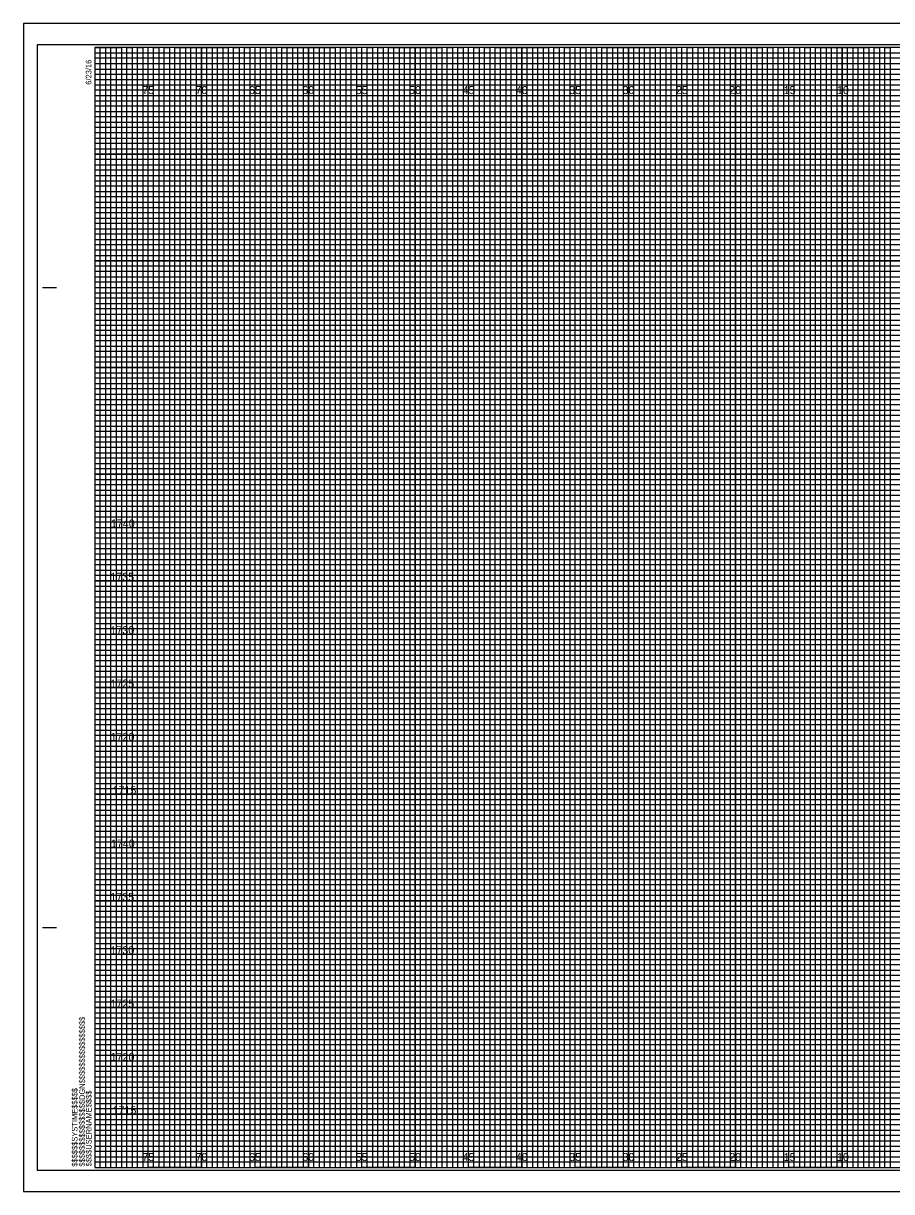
# Model space of a CAD drawing. Extents: x -7 to 162, y -2 to 327.
# Drawn here: x -6.7 to 74.6, y 217.7 to 327.2 of the extents above; entities that cross this region are included whole.
import ezdxf

# ---------------------------------------------------------------- set-up
doc = ezdxf.new("R2010")
doc.units = 0
for name, color, linetype in [('Prop XS Elevation Labels', 7, 'Continuous'), ('Prop XS Offset Labels', 7, 'Continuous'), ('Sheet Cross Section CELL', 7, 'Continuous'), ('Sheet Cross Section Grid Major CELL', 7, 'Continuous'), ('Sheet Cross Section Grid Middle CELL', 7, 'Continuous'), ('Sheet Cross Section Grid Minor 1 CELL', 7, 'Continuous'), ('Sheet Cross Section Grid Minor 2 CELL', 7, 'Continuous'), ('Sheet Cutting Line CELL', 7, 'Continuous'), ('Sheet DOT Grid CELL', 7, 'Continuous'), ('Sheet Plot Border Inside CELL', 7, 'Continuous'), ('Sheet Plot Border Outside CELL', 7, 'Continuous')]:
    doc.layers.add(name, color=color, linetype=linetype)

msp = doc.modelspace()

# ---------------------------------------------------------------- linework, layer by layer
at = {"layer": 'Sheet Cross Section CELL'}
for p, q in [((-4.9, 302.5), (-3.65, 302.5)), ((-4.85, 302.5), (-3.6, 302.5)), ((-4.9, 242.5), (-3.65, 242.5)), ((-4.85, 242.5), (-3.6, 242.5)), ((0, 220), (0, 220)), ((0, 220), (0, 220)), ((0, 220), (0, 220)), ((0, 220), (0, 220)), ((0, 220), (0, 220)), ((0, 220), (0, 220)), ((0, 220), (0, 220))]:
    msp.add_line(p, q, dxfattribs=at)
msp.add_lwpolyline([(160, 325), (0, 325), (0, 220), (160, 220)], close=True, dxfattribs=at)
at = {"layer": 'Sheet Cross Section Grid Major CELL'}
for p, q in [((5, 325), (0, 325)), ((5, 220), (5, 325)), ((15, 325), (10, 325)), ((10, 325), (10, 220)), ((15, 220), (15, 325)), ((25, 325), (20, 325)), ((20, 325), (20, 220)), ((25, 220), (25, 325)), ((35, 325), (30, 325)), ((30, 325), (30, 220)), ((35, 220), (35, 325)), ((45, 325), (40, 325)), ((40, 325), (40, 220)), ((45, 220), (45, 325)), ((55, 325), (50, 325)), ((50, 325), (50, 220)), ((55, 220), (55, 325)), ((65, 325), (60, 325)), ((60, 325), (60, 220)), ((65, 220), (65, 325)), ((75, 325), (70, 325)), ((70, 325), (70, 220)), ((10, 220), (5, 220)), ((20, 220), (15, 220)), ((30, 220), (25, 220)), ((40, 220), (35, 220)), ((50, 220), (45, 220)), ((60, 220), (55, 220)), ((70, 220), (65, 220))]:
    msp.add_line(p, q, dxfattribs=at)
for points in [[(0, 320), (160, 320), (160, 315), (0, 315)], [(0, 310), (160, 310), (160, 305), (0, 305)], [(0, 300), (160, 300), (160, 295), (0, 295)], [(0, 290), (160, 290), (160, 285), (0, 285)], [(0, 280), (160, 280), (160, 275), (0, 275)], [(0, 270), (160, 270), (160, 265), (0, 265)], [(0, 260), (160, 260), (160, 255), (0, 255)], [(0, 250), (160, 250), (160, 245), (0, 245)], [(0, 240), (160, 240), (160, 235), (0, 235)], [(0, 230), (160, 230), (160, 225), (0, 225)]]:
    msp.add_lwpolyline(points, dxfattribs=at)
at = {"layer": 'Sheet Cross Section Grid Middle CELL'}
for points in [[(0, 325), (2.5, 325), (2.5, 220), (7.5, 220), (7.5, 325), (12.5, 325), (12.5, 220), (17.5, 220), (17.5, 325), (22.5, 325), (22.5, 220), (27.5, 220), (27.5, 325), (32.5, 325), (32.5, 220), (37.5, 220), (37.5, 325), (42.5, 325), (42.5, 220), (47.5, 220), (47.5, 325), (52.5, 325), (52.5, 220), (57.5, 220), (57.5, 325), (62.5, 325), (62.5, 220), (67.5, 220), (67.5, 325), (72.5, 325), (72.5, 220), (77.5, 220)], [(0, 322.5), (137.5, 322.5)], [(0, 312.5), (160, 312.5), (160, 317.5), (0, 317.5)], [(0, 302.5), (160, 302.5), (160, 307.5), (0, 307.5)], [(0, 292.5), (160, 292.5), (160, 297.5), (0, 297.5)], [(0, 282.5), (160, 282.5), (160, 287.5), (0, 287.5)], [(0, 272.5), (160, 272.5), (160, 277.5), (0, 277.5)], [(0, 262.5), (160, 262.5), (160, 267.5), (0, 267.5)], [(0, 252.5), (160, 252.5), (160, 257.5), (0, 257.5)], [(0, 242.5), (160, 242.5), (160, 247.5), (0, 247.5)], [(0, 232.5), (160, 232.5), (160, 237.5), (0, 237.5)], [(0, 222.5), (160, 222.5), (160, 227.5), (0, 227.5)]]:
    msp.add_lwpolyline(points, dxfattribs=at)
at = {"layer": 'Sheet Cross Section Grid Minor 1 CELL'}
for p, q in [((0, 324.5), (130, 324.5)), ((130, 323.99), (0, 323.99)), ((0, 323.99), (0, 323.5)), ((0, 323.5), (130, 323.5)), ((130, 322.94), (0, 322.94)), ((0, 322.94), (0, 322)), ((0, 322), (160, 322))]:
    msp.add_line(p, q, dxfattribs=at)
for points in [[(0, 321.5), (135, 321.5), (160, 321.5), (160, 321), (0, 321)], [(0, 320.5), (160, 320.5), (160, 319.5), (0, 319.5)], [(0, 319), (160, 319), (160, 318.5), (0, 318.49)], [(0, 318), (160, 318), (160, 317), (0, 317)], [(0, 316.5), (160, 316.5), (160, 316), (0, 316)], [(0, 315.5), (160, 315.5), (160, 314.5), (0, 314.5)], [(0, 314), (160, 314), (160, 313.5), (0, 313.5)], [(0, 313), (160, 313), (160, 312), (0, 312)], [(0, 311.5), (160, 311.5), (160, 311), (0, 311)], [(0, 310.5), (160, 310.5), (160, 309.5), (0, 309.5)], [(0, 309), (160, 309), (160, 308.5), (0, 308.5)], [(0, 308), (160, 308), (160, 306.98), (160, 306.5), (160, 306), (0, 306)], [(0, 307), (160, 307), (160, 306.5), (0, 306.5)], [(0, 305.5), (160, 305.5), (160, 304.5), (0, 304.51)], [(0, 304.51), (160, 304.5), (160, 304), (0, 304)], [(0, 303.5), (160, 303.5), (160, 303), (0, 303)], [(0, 302), (160, 302), (160, 301.5), (0, 301.5)], [(0, 301), (160, 301), (160, 300.5), (0, 300.5)], [(-0.04, 299.44), (160, 299.44), (160, 298.94), (-0.04, 298.94)], [(0, 298.5), (160, 298.5), (160, 298), (0, 298)], [(0, 297), (160, 297), (160, 296.5), (0, 296.5)], [(0, 296), (160, 296), (160, 295.5), (0, 295.5)], [(0, 294.5), (160, 294.5), (160, 294), (0, 294)], [(0, 293.5), (160, 293.5), (160, 293), (0, 293)], [(0, 292), (160, 292), (160, 291.5), (0, 291.5)], [(0, 291), (160, 291), (160, 290.5), (0, 290.5)], [(0, 289.5), (160, 289.5), (160, 288.99), (0, 289)], [(0, 288.5), (160, 288.5), (160, 288), (0, 288)], [(0, 287), (160, 287), (160, 286.5), (0, 286.5)], [(0, 286), (160, 286), (160, 285.5), (0, 285.5)], [(0, 284.5), (160, 284.5), (160, 284), (0, 284)], [(0, 283.5), (160, 283.5), (160, 283), (0, 283)], [(0, 282), (160, 282), (160, 281.5), (0, 281.5)], [(0, 281), (160, 281), (160, 280.5), (0, 280.5)], [(0, 279.5), (160, 279.5), (160, 279), (0, 279)], [(0, 278.5), (160.03, 278.45), (160, 278), (0, 278)], [(0, 277), (160, 277), (160, 276.5), (0, 276.5)], [(0, 276), (160, 276), (160, 275.5), (0, 275.5)], [(0, 274.5), (160, 274.5), (160, 274), (0, 274)], [(0, 273.5), (160, 273.5), (160, 273), (0, 273)], [(0, 272), (160, 272), (160, 271.5), (0, 271.5)], [(0, 271), (160, 271), (160, 270.5), (0, 270.5)], [(0, 269.5), (160, 269.5), (160, 269), (0, 269)], [(0, 268.5), (160, 268.5), (160, 268), (0, 268)], [(0, 267), (160, 267), (160, 266.5), (0, 266.5)], [(0, 266), (160, 266), (160, 265.5), (0, 265.5)], [(0, 264.5), (160, 264.5), (160, 264), (0, 264)], [(0, 263.5), (160, 263.5), (160, 263), (0, 263)], [(0, 262), (160, 262), (160, 261.5), (0, 261.5)], [(0, 261), (160, 261), (160, 260.5), (0, 260.5)], [(0, 259.5), (160, 259.5), (160, 258.99), (0, 259)], [(0, 258.5), (160, 258.5), (160, 258), (0, 258)], [(0, 257), (160, 257), (160, 256.5), (0, 256.5)], [(0, 256), (160, 256), (160, 255.5), (0, 255.5)], [(0, 254.5), (160, 254.5), (160, 254), (0, 254)], [(0, 253.5), (160, 253.5), (160, 253), (0, 253)], [(0, 252), (160, 252), (160, 251.5), (0, 251.5)], [(0, 251), (160, 251), (160, 250.5), (0, 250.5)], [(0, 249.5), (160, 249.5), (160, 249), (0, 249)], [(0, 248.5), (160.03, 248.46), (160, 248), (0, 248)], [(0, 247), (160, 247), (160, 246.5), (0, 246.5)], [(0, 246), (160, 246), (160, 245.5), (0, 245.5)], [(0, 244.5), (160, 244.5), (160, 244), (0, 244)], [(0, 243.5), (160, 243.5), (160, 243), (0, 243)], [(0, 242), (160, 242), (160, 241.5), (0, 241.5)], [(0, 241), (160, 241), (160, 240.5), (0, 240.5)], [(0, 239.5), (160, 239.5), (160, 239), (0, 239)], [(0, 238.5), (160, 238.5), (160, 238), (0, 238)], [(0, 237), (160, 237), (160, 236.5), (0, 236.5)], [(0, 236), (160, 236), (160, 235.5), (0, 235.5)], [(0, 234.5), (160, 234.5), (160, 234), (0, 234)], [(0, 233.5), (160, 233.5), (160, 233), (0, 233)], [(0, 232), (160, 232), (160, 231.5), (0, 231.5)], [(0, 231), (160, 231), (160, 230.5), (0, 230.5)], [(0, 229.5), (160, 229.5), (160, 229), (0, 229)], [(0, 228.5), (160, 228.5), (160, 228), (0, 228)], [(0, 227), (160, 227), (160, 226.5), (0, 226.5)], [(0, 226), (160, 226), (160, 225.5), (0, 225.5)], [(0, 224.5), (160, 224.5), (160, 224), (0, 224)], [(0, 223.5), (160, 223.5), (160, 223), (0, 223)], [(0, 222), (160, 222), (160, 221.5), (0, 221.5)], [(0, 221), (160, 221), (160, 220.5), (0, 220.5)]]:
    msp.add_lwpolyline(points, dxfattribs=at)
at = {"layer": 'Sheet Cross Section Grid Minor 2 CELL'}
for points in [[(0, 220), (0.5, 220), (0.5, 325), (1, 325), (1, 220)], [(1, 220), (1.5, 220), (1.5, 325), (2, 325), (2, 220)], [(2.5, 220), (3, 220), (3, 325), (3.5, 325), (3.5, 220)], [(3.5, 220), (4, 220), (4, 325), (4.5, 325), (4.5, 220)], [(5, 220), (5.5, 220), (5.5, 325), (6, 325), (6, 220)], [(6, 220), (6.5, 220), (6.5, 325), (7, 325), (7, 220)], [(7.5, 220), (8, 220), (8, 325), (8.5, 325), (8.5, 220)], [(8.5, 220), (9, 220), (9, 325), (9.5, 325), (9.5, 220)], [(10, 220), (10.5, 220), (10.5, 325), (11, 325), (11, 220)], [(11, 220), (11.5, 220), (11.5, 325), (12, 325), (12, 220)], [(12.5, 220), (13, 220), (13, 325), (13.5, 325), (13.5, 220)], [(13.5, 220), (14, 220), (14, 325), (14.5, 325), (14.5, 220)], [(15, 220), (15.5, 220), (15.5, 325), (16, 325), (16, 220)], [(16, 220), (16.5, 220), (16.5, 325), (17, 325), (17, 220)], [(17.5, 220), (18, 220), (18, 325), (18.5, 325), (18.5, 220)], [(18.5, 220), (19, 220), (19, 325), (19.5, 325), (19.5, 220)], [(20, 220), (20.5, 220), (20.5, 325), (21, 325), (21, 220)], [(21, 220), (21.5, 220), (21.5, 325), (22, 325), (22, 220)], [(22.5, 220), (23, 220), (23, 325), (23.5, 325), (23.5, 220)], [(23.5, 220), (24, 220), (24, 325), (24.5, 325), (24.5, 220)], [(25, 220), (25.5, 220), (25.5, 325), (26, 325), (26, 220)], [(26, 220), (26.5, 220), (26.5, 325), (27, 325), (27, 220)], [(27.5, 220), (28, 220), (28, 325), (28.5, 325), (28.5, 220)], [(28.5, 220), (29, 220), (29, 325), (29.5, 325), (29.5, 220)], [(30, 220), (30.5, 220), (30.5, 325), (31, 325), (31, 220)], [(31, 220), (31.5, 220), (31.5, 325), (32, 325), (32, 220)], [(32.5, 220), (33, 220), (33, 325), (33.5, 325), (33.5, 220)], [(33.5, 220), (34, 220), (34, 325), (34.5, 325), (34.5, 220)], [(35, 220), (35.5, 220), (35.5, 325), (36, 325), (36, 220)], [(36, 220), (36.5, 220), (36.5, 325), (37, 325), (37, 220)], [(37.5, 220), (38, 220), (38, 325), (38.5, 325), (38.5, 220)], [(38.5, 220), (39, 220), (39, 325), (39.5, 325), (39.5, 220)], [(40, 220), (40.5, 220), (40.5, 325), (41, 325), (41, 220)], [(41, 220), (41.5, 220), (41.5, 325), (42, 325), (42, 220)], [(42.5, 220), (43, 220), (43, 325), (43.5, 325), (43.5, 220)], [(43.5, 220), (44, 220), (44, 325), (44.5, 325), (44.5, 220)], [(45, 220), (45.5, 220), (45.5, 325), (46, 325), (46, 220)], [(46, 220), (46.5, 220), (46.5, 325), (47, 325), (47, 220)], [(47.5, 220), (48, 220), (48, 325), (48.5, 325), (48.5, 220)], [(48.5, 220), (49, 220), (49, 325), (49.5, 325), (49.5, 220)], [(50, 220), (50.5, 220), (50.5, 325), (51, 325), (51, 220)], [(51, 220), (51.5, 220), (51.5, 325), (52, 325), (52, 220)], [(52.5, 220), (53, 220), (53, 325), (53.5, 325), (53.5, 220)], [(53.5, 220), (54, 220), (54, 325), (54.5, 325), (54.5, 220)], [(55, 220), (55.5, 220), (55.5, 325), (56, 325), (56, 220)], [(56, 220), (56.5, 220), (56.5, 325), (57, 325), (57, 220)], [(57.5, 220), (58, 220), (58, 325), (58.5, 325), (58.5, 220)], [(58.5, 220), (59, 220), (59, 325), (59.5, 325), (59.5, 220)], [(60, 220), (60.5, 220), (60.5, 325), (61, 325), (61, 220)], [(61, 220), (61.5, 220), (61.5, 325), (62, 325), (62, 220)], [(62.5, 220), (63, 220), (63, 325), (63.5, 325), (63.5, 220)], [(63.5, 220), (64, 220), (64, 325), (64.5, 325), (64.5, 220)], [(65, 220), (65.5, 220), (65.5, 325), (66, 325), (66, 220)], [(66, 220), (66.5, 220), (66.5, 325), (67, 325), (67, 220)], [(67.5, 220), (68, 220), (68, 325), (68.5, 325), (68.5, 220)], [(68.5, 220), (69, 220), (69, 325), (69.5, 325), (69.5, 220)], [(70, 220), (70.5, 220), (70.5, 325), (71, 325), (71, 220)], [(71, 220), (71.5, 220), (71.5, 325), (72, 325), (72, 220)], [(72.5, 220), (73, 220), (73, 325), (73.5, 325), (73.5, 220)], [(73.5, 220), (74, 220), (74, 325), (74.5, 325), (74.5, 220)]]:
    msp.add_lwpolyline(points, dxfattribs=at)
at = {"layer": 'Sheet Cutting Line CELL'}
for p, q in [((161.65, 327.25), (-6.7, 327.25)), ((-6.7, 327.25), (-6.7, 217.75)), ((-6.7, 217.75), (161.65, 217.75))]:
    msp.add_line(p, q, dxfattribs=at)
at = {"layer": 'Sheet DOT Grid CELL'}
for p, q in [((5, 220), (5, 325)), ((10, 220), (10, 325)), ((15, 220), (15, 325)), ((20, 220), (20, 325)), ((25, 220), (25, 325)), ((30, 220), (30, 325)), ((35, 220), (35, 325)), ((40, 220), (40, 325)), ((45, 220), (45, 325)), ((50, 220), (50, 325)), ((55, 220), (55, 325)), ((60, 220), (60, 325)), ((65, 220), (65, 325)), ((70, 220), (70, 325)), ((0, 320), (160, 320)), ((0, 315), (160, 315)), ((0, 310), (160, 310)), ((0, 305), (160, 305)), ((0, 300), (160, 300)), ((0, 295), (160, 295)), ((0, 290), (160, 290)), ((0, 285), (160, 285)), ((0, 280), (160, 280)), ((0, 275), (160, 275)), ((0, 270), (160, 270)), ((0, 265), (160, 265)), ((0, 260), (160, 260)), ((0, 255), (160, 255)), ((0, 250), (160, 250)), ((0, 245), (160, 245)), ((0, 240), (160, 240)), ((0, 235), (160, 235)), ((0, 230), (160, 230)), ((0, 225), (160, 225))]:
    msp.add_line(p, q, dxfattribs=at)
at = {"layer": 'Sheet Plot Border Inside CELL'}
msp.add_lwpolyline([(-5.4, 219.75), (161.2, 219.75), (161.2, 325.25), (-5.4, 325.25)], close=True, dxfattribs=at)
at = {"layer": 'Sheet Plot Border Outside CELL'}
msp.add_lwpolyline([(-6.7, 217.75), (161.65, 217.75), (161.65, 327.25), (-6.7, 327.25)], close=True, dxfattribs=at)

# ---------------------------------------------------------------- texts
at = {"layer": 'Prop XS Elevation Labels'}
for s, p in [('1740', (1.5, 280)), ('1735', (1.45, 275)), ('1730', (1.46, 270)), ('1725', (1.46, 265)), ('1720', (1.47, 260)), ('1715', (1.65, 255)), ('1740', (1.5, 250)), ('1735', (1.45, 245)), ('1730', (1.46, 240)), ('1725', (1.46, 235)), ('1720', (1.47, 230)), ('1715', (1.65, 225))]:
    msp.add_text(s, height=0.75, dxfattribs=at).set_placement(p)
at = {"layer": 'Prop XS Offset Labels'}
for s, p in [('75', (4.44, 320.62)), ('70', (9.43, 320.62)), ('65', (14.44, 320.62)), ('60', (19.43, 320.62)), ('55', (24.44, 320.62)), ('50', (29.43, 320.62)), ('45', (34.44, 320.62)), ('40', (39.43, 320.62)), ('35', (44.44, 320.62)), ('30', (49.43, 320.62)), ('25', (54.44, 320.62)), ('20', (59.43, 320.62)), ('15', (64.53, 320.62)), ('10', (69.52, 320.62)), ('75', (4.44, 220.62)), ('70', (9.43, 220.62)), ('65', (14.44, 220.62)), ('60', (19.43, 220.62)), ('55', (24.44, 220.62)), ('50', (29.43, 220.62)), ('45', (34.44, 220.62)), ('40', (39.43, 220.62)), ('35', (44.44, 220.62)), ('30', (49.43, 220.62)), ('25', (54.44, 220.62)), ('20', (59.43, 220.62)), ('15', (64.53, 220.62)), ('10', (69.52, 220.62))]:
    msp.add_text(s, height=0.75, dxfattribs=at).set_placement(p)
at = {"layer": 'Sheet Cross Section CELL'}
for s, p in [('6/23/16', (-0.33, 321.5)), ('$$$$$$$$$$$$$$$$DGN$$$$$$$$$$$$$$$$', (-0.94, 220.09)), ('$$$$$$SYSTIME$$$$$', (-1.63, 220.09)), ('$$$$USERNAME$$$$', (-0.31, 220.12))]:
    msp.add_text(s, height=0.525, rotation=90, dxfattribs=at).set_placement(p)

doc.saveas('drawing.dxf')
